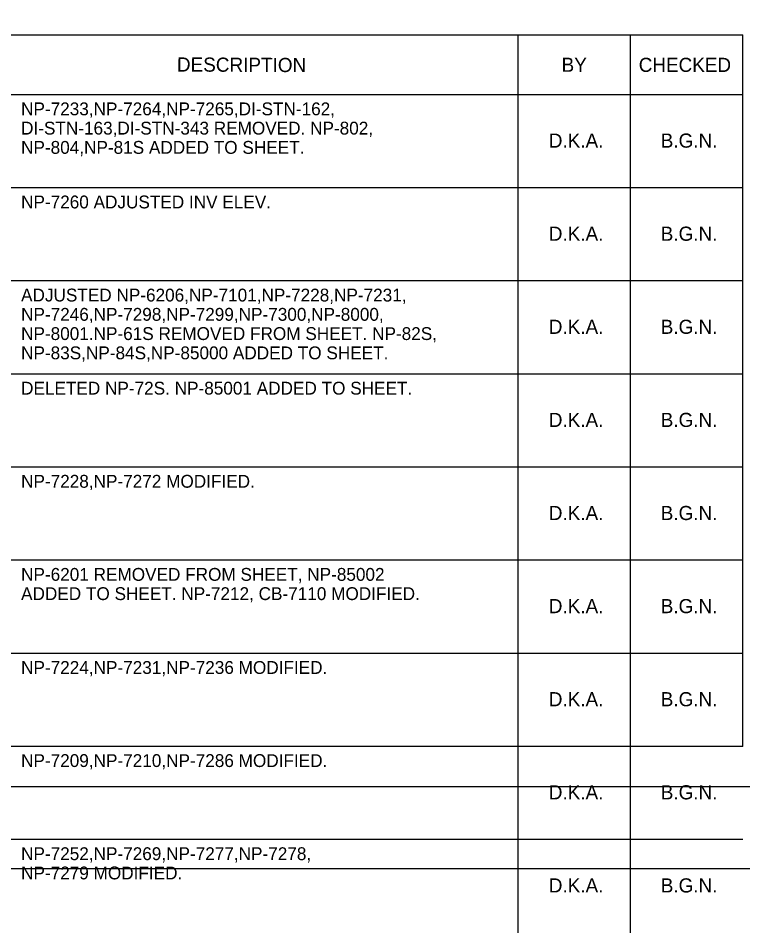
# Model space of a CAD drawing. Extents: x 260980 to 262786, y 322332 to 323393.
# Drawn here: x 262339.5 to 262565.2, y 322331.9 to 322616.8 of the extents above; entities that cross this region are included whole.
import ezdxf

# ---------------------------------------------------------------- set-up
doc = ezdxf.new("R2010")
doc.units = 0
for name, color, linetype in [('Level 23', 7, 'Continuous'), ('Level 5', 7, 'Continuous'), ('RD_SHT_TX', 7, 'Continuous')]:
    doc.layers.add(name, color=color, linetype=linetype)

msp = doc.modelspace()

# ---------------------------------------------------------------- linework, layer by layer
at = {"layer": 'Level 23'}
msp.add_lwpolyline([(261111.06, 323336.45), (262761.54, 323336.45), (262761.54, 322351.79), (261111.06, 322351.79)], close=True, dxfattribs=at)
msp.add_lwpolyline([(261111.06, 323336.45), (262761.54, 323336.45), (262761.54, 322351.79), (261111.06, 322351.79)], close=True, dxfattribs=at)
at = {"layer": 'Level 5'}
msp.add_lwpolyline([(261111.06, 323310.45), (262762.33, 323310.45), (262762.33, 322377.34), (261111.06, 322377.34)], close=True, dxfattribs=at)
at = {"layer": 'RD_SHT_TX'}
for p, q in [((262254.62, 322611.63), (262565.22, 322611.63)), ((262495.22, 322331.93), (262495.22, 322611.63)), ((262530.22, 322331.93), (262530.22, 322611.63)), ((262565.22, 322389.93), (262565.22, 322611.63)), ((262565.22, 322592.93), (261944.02, 322592.93)), ((262565.22, 322563.93), (261944.02, 322563.93)), ((262565.22, 322563.93), (261944.02, 322563.93)), ((262565.22, 322534.93), (261944.02, 322534.93)), ((262565.22, 322505.93), (261944.02, 322505.93)), ((262565.22, 322476.93), (261944.02, 322476.93)), ((262565.22, 322447.93), (261944.02, 322447.93)), ((262565.22, 322418.93), (261944.02, 322418.93)), ((262565.22, 322389.93), (261944.02, 322389.93)), ((262565.22, 322360.93), (261944.02, 322360.93))]:
    msp.add_line(p, q, dxfattribs=at)

# ---------------------------------------------------------------- texts
for s, height, rotation, p in [('DESCRIPTION', 4.4083, 359.7246, (262388.92, 322600.17)), ('BY', 4.408, 359.7246, (262508.77, 322600.09)), ('NP-7233,NP-7264,NP-7265,DI-STN-162,', 4, 360, (262340.37, 322586.54)), ('DI-STN-163,DI-STN-343 REMOVED. NP-802,', 4, 360, (262340.37, 322580.54)), ('B.G.N.', 4.4, 360, (262539.68, 322576.46)), ('NP-804,NP-81S ADDED TO SHEET.', 4, 360, (262340.37, 322574.54)), ('D.K.A.', 4.4, 360, (262504.81, 322576.46)), ('NP-7260 ADJUSTED INV ELEV.', 4, 360, (262340.37, 322557.54)), ('D.K.A.', 4.4, 360, (262504.81, 322547.46)), ('B.G.N.', 4.4, 360, (262539.68, 322547.46)), ('ADJUSTED NP-6206,NP-7101,NP-7228,NP-7231,', 4, 360, (262340.37, 322528.54)), ('NP-7246,NP-7298,NP-7299,NP-7300,NP-8000,', 4, 360, (262340.37, 322522.54)), ('D.K.A.', 4.4, 360, (262504.81, 322518.46)), ('B.G.N.', 4.4, 360, (262539.68, 322518.46)), ('NP-8001.NP-61S REMOVED FROM SHEET. NP-82S,', 4, 360, (262340.37, 322516.54)), ('NP-83S,NP-84S,NP-85000 ADDED TO SHEET.', 4, 360, (262340.37, 322510.54)), ('DELETED NP-72S. NP-85001 ADDED TO SHEET.', 4, 360, (262340.37, 322499.54)), ('D.K.A.', 4.4, 360, (262504.81, 322489.46)), ('B.G.N.', 4.4, 360, (262539.68, 322489.46)), ('NP-7228,NP-7272 MODIFIED.', 4, 360, (262340.37, 322470.54)), ('D.K.A.', 4.4, 360, (262504.81, 322460.46)), ('B.G.N.', 4.4, 360, (262539.68, 322460.46)), ('NP-6201 REMOVED FROM SHEET, NP-85002 ', 4, 360, (262340.37, 322441.54)), ('ADDED TO SHEET. NP-7212, CB-7110 MODIFIED.', 4, 360, (262340.37, 322435.54)), ('D.K.A.', 4.4, 360, (262504.81, 322431.46)), ('B.G.N.', 4.4, 360, (262539.68, 322431.46)), ('NP-7224,NP-7231,NP-7236 MODIFIED.', 4, 360, (262340.37, 322412.54)), ('D.K.A.', 4.4, 360, (262504.81, 322402.46)), ('B.G.N.', 4.4, 360, (262539.68, 322402.46)), ('NP-7209,NP-7210,NP-7286 MODIFIED.', 4, 360, (262340.37, 322383.54)), ('D.K.A.', 4.4, 360, (262504.81, 322373.46)), ('B.G.N.', 4.4, 360, (262539.69, 322373.46)), ('NP-7252,NP-7269,NP-7277,NP-7278,', 4, 360, (262340.37, 322354.54)), ('NP-7279 MODIFIED.', 4, 360, (262340.37, 322348.54)), ('D.K.A.', 4.4, 360, (262504.81, 322344.46)), ('B.G.N.', 4.4, 360, (262539.69, 322344.46))]:
    msp.add_text(s, height=height, rotation=rotation, dxfattribs=at).set_placement(p)
msp.add_text('CHECKED', height=4.4, dxfattribs=at).set_placement((262532.82, 322600.05))

doc.saveas('drawing.dxf')
